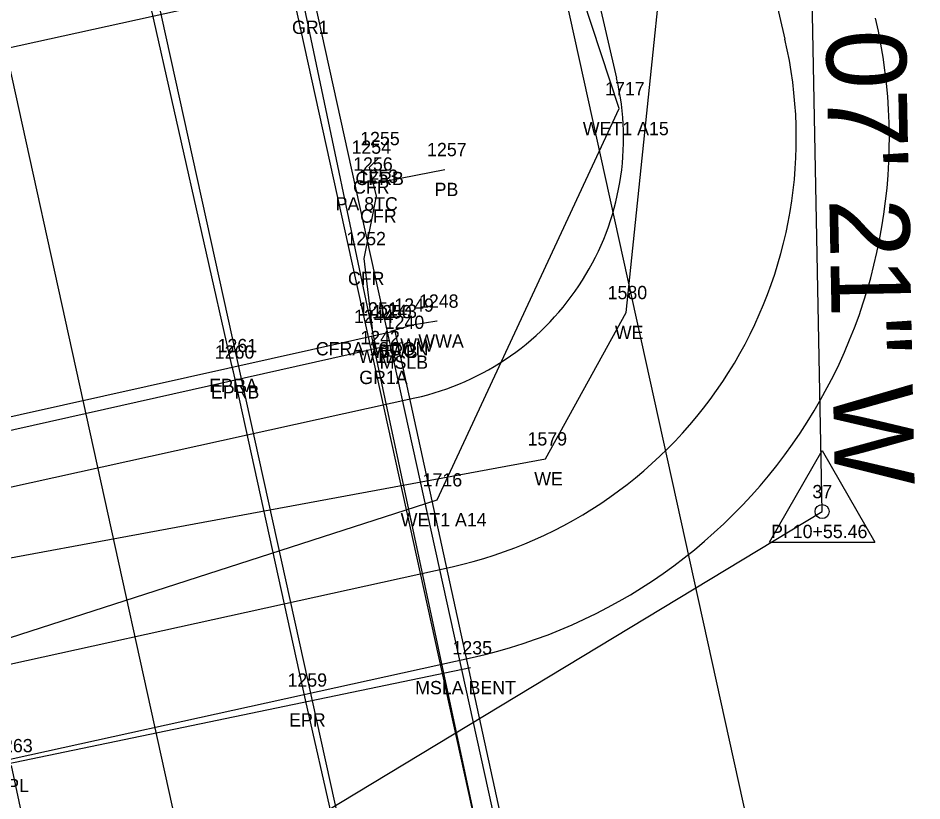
# Model space of a CAD drawing. Extents: x 2520975 to 2526538, y 881018 to 888064.
# Drawn here: x 2523776.7 to 2523844.7, y 885126.5 to 885185.4 of the extents above; entities that cross this region are included whole.
import ezdxf

# ---------------------------------------------------------------- set-up
doc = ezdxf.new("R2010")
doc.units = 0
for name, color, linetype in [('RD_EV_JurisArea', 7, 'Continuous'), ('RD_EX_BldgApp', 7, 'Continuous'), ('RD_EX_BldgApp_txCode', 7, 'Continuous'), ('RD_EX_Bridge', 7, 'Continuous'), ('RD_EX_Bridge_txCode', 7, 'Continuous'), ('RD_EX_Conc', 7, 'Continuous'), ('RD_EX_Conc_txCode', 7, 'Continuous'), ('RD_EX_DR_Pipe', 7, 'Continuous'), ('RD_EX_DR_Pipe_txCode', 7, 'Continuous'), ('RD_EX_GuardRail', 7, 'Continuous'), ('RD_EX_GuardRail_txCode', 7, 'Continuous'), ('RD_EX_H2O', 7, 'Continuous'), ('RD_EX_H2O_txCode', 7, 'Continuous'), ('RD_EX_H2O_WetLd_txCode', 7, 'Continuous'), ('RD_EX_Misc', 7, 'Continuous'), ('RD_EX_Misc_txCode', 7, 'Continuous'), ('RD_EX_Road', 7, 'Continuous'), ('RD_EX_Road_txCode', 7, 'Continuous'), ('RD_HC_Cl', 7, 'Continuous'), ('RD_HC_Data', 7, 'Continuous'), ('RD_HC_txCode', 7, 'Continuous'), ('RD_PD_BCA', 7, 'Continuous'), ('RD_PD_Bridge', 7, 'Continuous'), ('RD_PD_CstnLmt', 7, 'Continuous'), ('RD_PD_DR_ErosCtrl', 7, 'Continuous'), ('RD_PD_Final_TrvlWay', 7, 'Continuous'), ('RD_SMD_Locator', 7, 'Continuous')]:
    doc.layers.add(name, color=color, linetype=linetype)

msp = doc.modelspace()

# ---------------------------------------------------------------- linework, layer by layer
at = {"layer": 'RD_EV_JurisArea'}
msp.add_lwpolyline([(2523761.167, 885134.03), (2523808.209, 885149.207), (2523821.914, 885178.637), (2523802.851, 885236.548), (2523777.81, 885305.562), (2523748.196, 885444.322), (2523730.68, 885516.876), (2523708.637, 885617.3), (2523698.714, 885662.019), (2523727.827, 885665.815), (2523757.297, 885671.751)], dxfattribs=at)
at = {"layer": 'RD_EX_BldgApp'}
msp.add_lwpolyline([(2523819.439, 885087.441), (2523811.319, 885123.961), (2523803.308, 885161.503)], dxfattribs=at)
at = {"layer": 'RD_EX_Bridge'}
for points in [[(2523808.195, 885162.657), (2523806.339, 885162.355), (2523804.708, 885161.862)], [(2523774.906, 885077.596), (2523821.197, 885087.829), (2523805.064, 885161.895), (2523758.145, 885151.437), (2523774.906, 885077.596)]]:
    msp.add_lwpolyline(points, dxfattribs=at)
at = {"layer": 'RD_EX_Conc'}
msp.add_lwpolyline([(2523803.338, 885162.07), (2523802.732, 885167.359), (2523803.647, 885172.05), (2523803.117, 885174.241), (2523803.77, 885174.887)], dxfattribs=at)
at = {"layer": 'RD_EX_DR_Pipe'}
msp.add_line((2523803.266, 885172.973), (2523808.803, 885174.059), dxfattribs=at)
at = {"layer": 'RD_EX_GuardRail'}
msp.add_lwpolyline([(2523803.786, 885159.912), (2523798.239, 885186.256), (2523787.795, 885236.892)], dxfattribs=at)
at = {"layer": 'RD_EX_H2O'}
msp.add_lwpolyline([(2523738.909, 885147.498), (2523743.695, 885138.843), (2523816.359, 885152.29), (2523822.427, 885163.299), (2523826.928, 885206.612)], dxfattribs=at)
at = {"layer": 'RD_EX_Misc'}
for p, q in [((2523758.452, 885150.465), (2523805.656, 885161.063)), ((2523810.713, 885136.574), (2523763.829, 885126.803))]:
    msp.add_line(p, q, dxfattribs=at)
at = {"layer": 'RD_EX_Road'}
for p, q in [((2523792.777, 885159.311), (2523771.239, 885254.787)), ((2523792.894, 885158.826), (2523792.777, 885159.311)), ((2523798.302, 885134.145), (2523792.894, 885158.826)), ((2523803.791, 885109.941), (2523798.302, 885134.145)), ((2523781.516, 885104.768), (2523776.178, 885129.21))]:
    msp.add_line(p, q, dxfattribs=at)
at = {"layer": 'RD_HC_Cl'}
for p, q in [((2523662.651, 885798.932), (2524219.244, 883271.288)), ((2523641.165, 885794.201), (2524197.759, 883266.557)), ((2523837.18, 885148.323), (2523836.106, 885203.1)), ((2523672.044, 885048.634), (2523837.18, 885148.323))]:
    msp.add_line(p, q, dxfattribs=at)
at = {"layer": 'RD_HC_Data'}
for p, q in [((2523833.209, 885146.03), (2523837.181, 885152.909)), ((2523837.181, 885152.909), (2523841.149, 885146.03)), ((2523833.209, 885146.03), (2523841.149, 885146.03))]:
    msp.add_line(p, q, dxfattribs=at)
msp.add_circle((2523837.18, 885148.323), 0.529, dxfattribs=at)
at = {"layer": 'RD_PD_BCA'}
msp.add_lwpolyline([(2523762.054, 885126.595), (2523810.84, 885137.338)], dxfattribs=at)
msp.add_arc((2523802.238, 885176.402), 40, 282.41848, 13.07237, dxfattribs=at)
at = {"layer": 'RD_PD_Bridge'}
for points in [[(2523798.673, 885188.194), (2523752.772, 885178.086)], [(2523826.629, 885061.235), (2523798.673, 885188.194)]]:
    msp.add_lwpolyline(points, dxfattribs=at)
at = {"layer": 'RD_PD_CstnLmt'}
msp.add_line((2523810.511, 885229.196), (2523821.719, 885180.926), dxfattribs=at)
msp.add_lwpolyline([(2523757.753, 885146.127), (2523806.539, 885156.87)], dxfattribs=at)
msp.add_arc((2523802.238, 885176.402), 20, 282.41848, 13.07237, dxfattribs=at)
at = {"layer": 'RD_PD_DR_ErosCtrl'}
msp.add_line((2523823.174, 885232.137), (2523834.383, 885183.866), dxfattribs=at)
msp.add_lwpolyline([(2523760.548, 885133.431), (2523809.334, 885144.174)], dxfattribs=at)
msp.add_arc((2523802.238, 885176.402), 33, 282.41848, 13.07237, dxfattribs=at)
at = {"layer": 'RD_PD_Final_TrvlWay'}
for p, q in [((2523712.872, 885663.865), (2524066.737, 884056.869)), ((2523720.239, 885490.907), (2524037.438, 884050.417))]:
    msp.add_line(p, q, dxfattribs=at)
at = {"layer": 'RD_SMD_Locator'}
for centre in [(2523821.914, 885178.637), (2523803.77, 885174.887), (2523803.117, 885174.241), (2523808.803, 885174.059), (2523803.266, 885172.973), (2523803.647, 885172.05), (2523802.732, 885167.359), (2523822.427, 885163.299), (2523806.339, 885162.355), (2523808.195, 885162.657), (2523803.338, 885162.07), (2523804.708, 885161.862), (2523805.064, 885161.895), (2523803.308, 885161.503), (2523805.656, 885161.063), (2523803.786, 885159.912), (2523792.777, 885159.311), (2523792.894, 885158.826), (2523816.359, 885152.29), (2523808.209, 885149.207), (2523837.18, 885148.323), (2523810.713, 885136.574), (2523798.302, 885134.145)]:
    msp.add_circle(centre, 0.001, dxfattribs=at)

# ---------------------------------------------------------------- texts
at = {"layer": 'RD_EX_BldgApp_txCode'}
for s, p in [('1244', (2523801.961, 885162.503)), ('W1B', (2523802.3, 885159.503))]:
    msp.add_text(s, height=1, dxfattribs=at).set_placement(p)
at = {"layer": 'RD_EX_Bridge_txCode'}
for s, p in [('1249', (2523804.993, 885163.355)), ('1248', (2523806.848, 885163.657)), ('1250', (2523803.323, 885162.862)), ('1243', (2523803.718, 885162.895)), ('WWA', (2523806.801, 885160.657)), ('BRC', (2523803.812, 885159.895)), ('WW', (2523805.434, 885160.355)), ('WWB', (2523803.33, 885159.862))]:
    msp.add_text(s, height=1, dxfattribs=at).set_placement(p)
at = {"layer": 'RD_EX_Conc_txCode'}
for s, p in [('1255', (2523802.423, 885175.887)), ('1254', (2523801.77, 885175.241)), ('CFRB', (2523802.069, 885172.887)), ('1253', (2523802.301, 885173.05)), ('CFR', (2523801.888, 885172.241)), ('CFR', (2523802.419, 885170.05)), ('1252', (2523801.386, 885168.359)), ('CFR', (2523801.504, 885165.359)), ('1251', (2523802.275, 885163.07)), ('CFRA 18CON', (2523799.086, 885160.07))]:
    msp.add_text(s, height=1, dxfattribs=at).set_placement(p)
at = {"layer": 'RD_EX_DR_Pipe_txCode'}
for s, p in [('1257', (2523807.457, 885175.059)), ('1256', (2523801.896, 885173.973)), ('PB', (2523808.024, 885172.059)), ('PA 8TC', (2523800.573, 885170.973))]:
    msp.add_text(s, height=1, dxfattribs=at).set_placement(p)
at = {"layer": 'RD_EX_GuardRail_txCode'}
for s, p in [('GR1', (2523797.294, 885184.256)), ('1242', (2523802.439, 885160.912)), ('GR1A', (2523802.353, 885157.912))]:
    msp.add_text(s, height=1, dxfattribs=at).set_placement(p)
at = {"layer": 'RD_EX_H2O_txCode'}
for s, p in [('1580', (2523821.041, 885164.299)), ('WE', (2523821.588, 885161.299)), ('1579', (2523815.013, 885153.29)), ('WE', (2523815.521, 885150.29))]:
    msp.add_text(s, height=1, dxfattribs=at).set_placement(p)
at = {"layer": 'RD_EX_H2O_WetLd_txCode'}
for s, p in [('1717', (2523820.851, 885179.637)), ('WET1 A15', (2523819.174, 885176.637)), ('1716', (2523807.123, 885150.207)), ('WET1 A14', (2523805.469, 885147.207))]:
    msp.add_text(s, height=1, dxfattribs=at).set_placement(p)
at = {"layer": 'RD_EX_Misc_txCode'}
for s, p in [('1240', (2523804.27, 885162.063)), ('MSLB', (2523803.892, 885159.063)), ('1235', (2523809.366, 885137.574)), ('MSLA BENT', (2523806.563, 885134.574))]:
    msp.add_text(s, height=1, dxfattribs=at).set_placement(p)
at = {"layer": 'RD_EX_Road_txCode'}
for s, p in [('1261', (2523791.691, 885160.311)), ('1260', (2523791.484, 885159.826)), ('EPRA', (2523791.061, 885157.311)), ('EPRB', (2523791.193, 885156.826)), ('1259', (2523796.956, 885135.145)), ('EPR', (2523797.074, 885132.145)), ('1263', (2523774.808, 885130.21)), ('EPL', (2523774.974, 885127.21))]:
    msp.add_text(s, height=1, dxfattribs=at).set_placement(p)
at = {"layer": 'RD_HC_Data'}
msp.add_text('N 1%%d 07\' 21" W', height=6, rotation=271.12261, dxfattribs=at).set_placement((2523837.119, 885202.44))
at = {"layer": 'RD_HC_txCode'}
for s, p in [('37', (2523836.447, 885149.323)), ('PI 10+55.46', (2523833.337, 885146.323))]:
    msp.add_text(s, height=1, dxfattribs=at).set_placement(p)

doc.saveas('drawing.dxf')
